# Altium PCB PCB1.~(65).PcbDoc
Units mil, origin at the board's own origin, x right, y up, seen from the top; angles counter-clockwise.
Board outline 6000 x 4000 mil, 2 copper layers (Top Layer, Bottom Layer); 40 components, 29 nets, 164 pads, 123 vias.
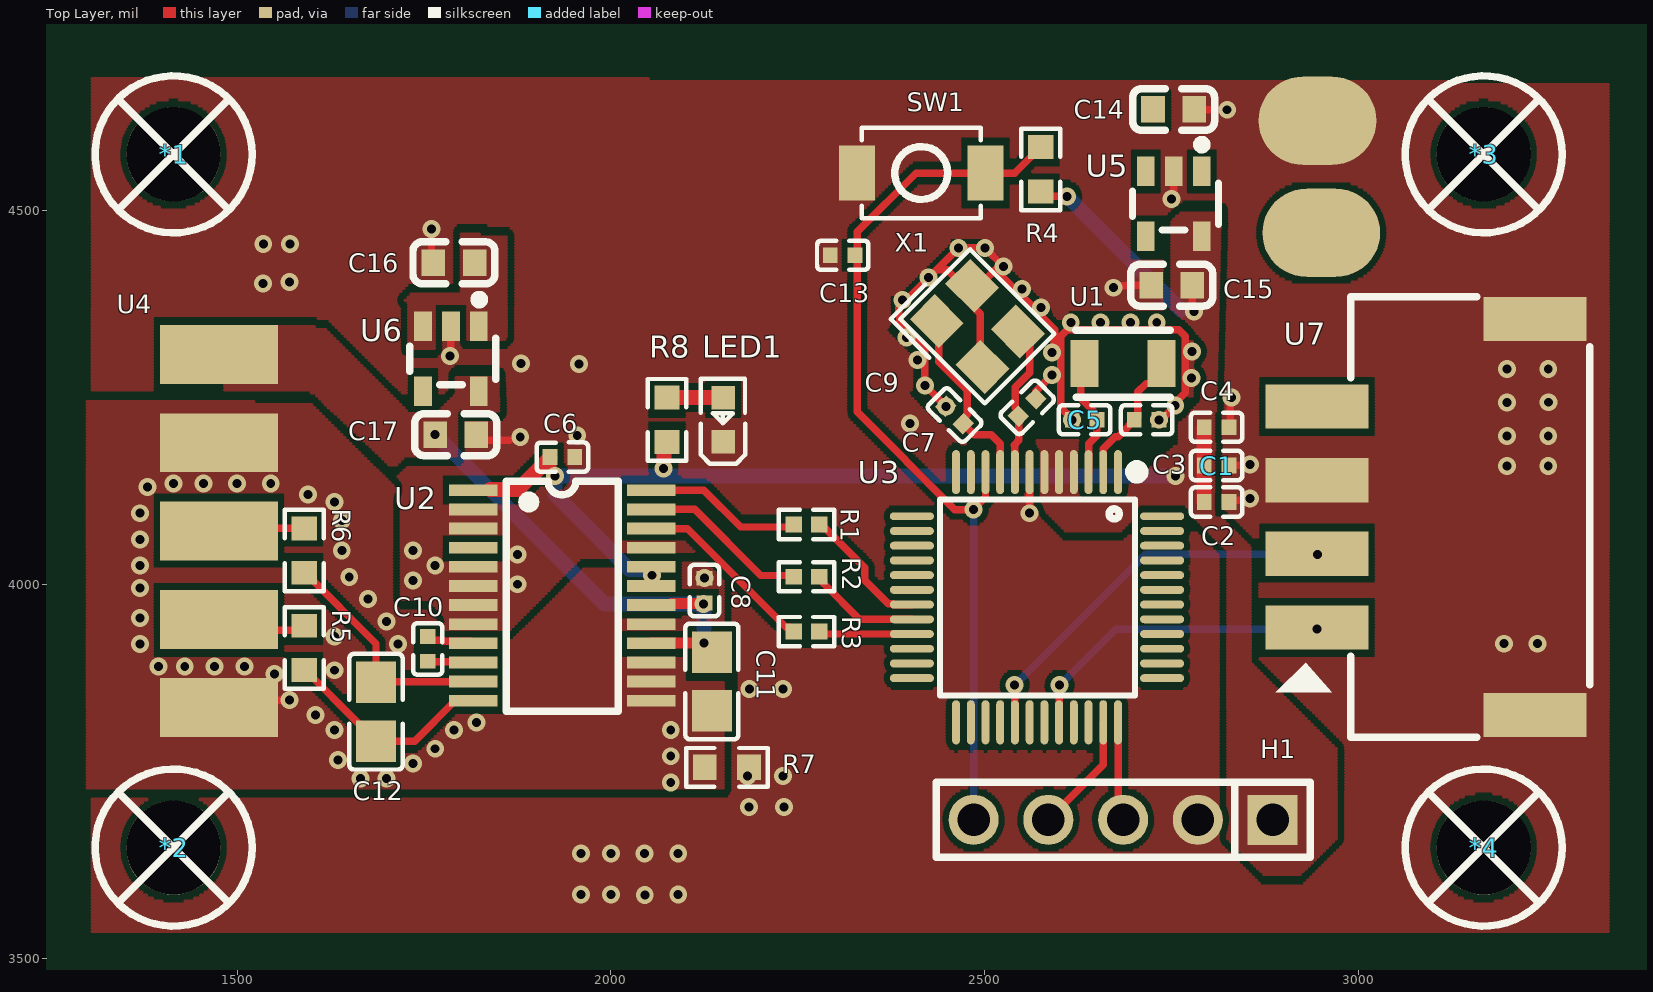
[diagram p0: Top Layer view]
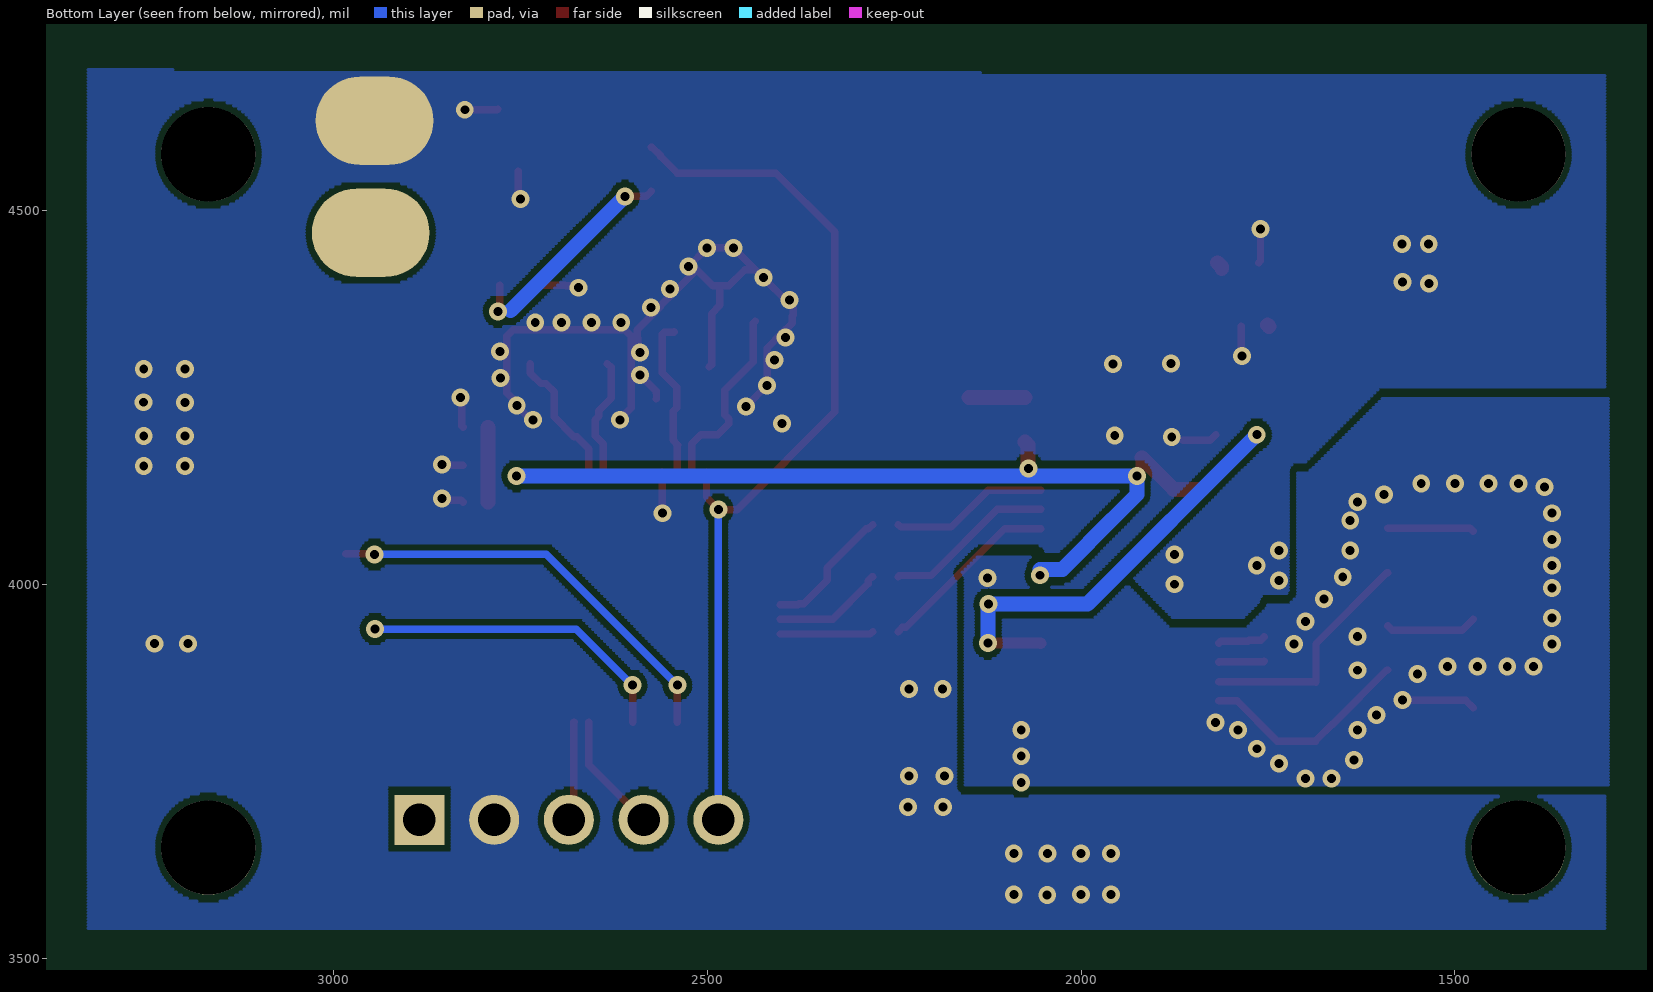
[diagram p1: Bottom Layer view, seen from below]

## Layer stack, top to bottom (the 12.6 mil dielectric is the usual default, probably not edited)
Top Solder: solder mask 0.4, Solder Resist, Dk 3.5
Top Layer: signal copper 1.4
Dielectric 1: dielectric 12.6, FR-4, Dk 4.8
Bottom Layer: signal copper 1.4
Bottom Solder: solder mask 0.4, Solder Resist, Dk 3.5

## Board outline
1000,1000 7000,1000 7000,5000 1000,5000

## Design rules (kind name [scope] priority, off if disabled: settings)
Clearance [All] p1: gap=8 ignorepadtopadclearanceinfootprint=FALSE
ComponentClearance [All] p1: gap=0 collisioncheckmode=3 verticalgap=0 showdistances=FALSE
HoleSize [All] p1: absolutevalues=TRUE maxlimit=130 minlimit=1 maxpercent=80.000 minpercent=20.000
MinimumSolderMaskSliver [All] p1: minsoldermaskwidth=4
PlaneConnect [All] p1: planeconnectstyle=Direct reliefexpansion=20 reliefentries=4 reliefconductorwidth=10 reliefairgap=10
PolygonConnect [All] p1: connectstyle=Direct reliefconductorwidth=10 reliefentries=4 polygonreliefangle="90 Angle" airgapwidth=10
RoutingVias [All] p1: holewidth=28 width=50 viastyle="Through Hole" minholewidth=28 minwidth=50 maxholewidth=28 maxwidth=50
SilkToSilkClearance [All] p1: silktosilkclearance=2
SilkToSolderMaskClearance [IsPad] p1: minsilkscreentomaskgap=2 clearancetoexposedcopper=TRUE
SolderMaskExpansion [All] p1: expansion=0 istentingtop=FALSE
SupplyNets "Schematic Supply Nets_2" [InNet('6V')] p1: voltage=0.000
SupplyNets "Schematic Supply Nets" [InNet('3V3')] p2: voltage=0.000
SupplyNets "Schematic Supply Nets_4" [InNet('5V')] p3: voltage=0.000
SupplyNets "Schematic Supply Nets_3" [InNet('DGND')] p4: voltage=0.000
SupplyNets "Schematic Supply Nets_1" [InNet('AGND')] p5: voltage=0.000
Width [All] p1: maxlimit=50 minlimit=10 preferedwidth=10
24 further rules are at their usual default settings.

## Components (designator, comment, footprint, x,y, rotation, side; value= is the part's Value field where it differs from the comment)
*1 "螺丝孔_1" M3螺丝 1415,4575 r0 top
*2 "螺丝孔_1" M3螺丝 1415,3647.74 r0 top
*3 "螺丝孔_1" M3螺丝 3167.2,4575 r0 top
*4 "螺丝孔_1" M3螺丝 3167.2,3647.74 r0 top
C1 "cc0402krx7r7bb104" C0402 2810,4158.83 r0 top value=100nF
C2 "cc0402jrnpo9bn220" C0402 2716.54,4220 r180 top value=22pF
C3 "cc0402krx7r7bb104" C0402 2810,4110 r0 top value=100nF
C4 "cc0402krx7r7bb104" C0402 2810,4210 r180 top value=100nF
C5 "cc0402jrnpo9bn220" C0402 2633.46,4220 r0 top value=22pF
C6 "cc0402krx7r7bb104" C0402 1935,4170 r0 top value=100nF
C7 "cc0402jrnpo9bn180" C0402 2556.7,4236.7 r45 top value=18pF
C8 "cc0402krx7r7bb104" C0402 2125,3991.54 r90 top value=100nF
C9 "cc0402jrnpo9bn180" C0402 2459.68,4226.29 r315 top value=18pF
C10 "cc0402krx7r7bb104" C0402 1755,3913.46 r90 top value=100nF
C11 "cl21b103kbannnc" C0805 2135,3870 r270 top value=10nF
C12 "cl21b103kbannnc" C0805 1685.78,3829.55 r270 top value=10nF
C13 "cc0402krx7r7bb104" C0402 2310,4440 r0 top value=100nF
C14 "cga0603x5r105k500jt" C0603 2752.56,4635 r0 top value=1uF
C15 "cga0603x5r105k500jt" C0603 2750,4400 r180 top value=1uF
C16 "cga0603x5r105k500jt" C0603 1790,4430 r180 top value=1uF
C17 "cga0603x5r105k500jt" C0603 1792.44,4200 r0 top value=1uF
H1 "pz254v-11-05p" HDR-TH_5P-P2.54-V-M 2685,3685 r180 top
LED1 "ltst-c190kskt" LED0603-RD 2150,4220 r90 top
R1 "frc0402f47r0ts" R0402 2261.76,4079.9 r0 top value=47Ω
R2 "frc0402f47r0ts" R0402 2261.76,4010.1 r0 top value=47Ω
R3 "frc0402f47r0ts" R0402 2261.76,3936.58 r0 top value=47Ω
R4 "frc0603f1002ts" R0603 2575,4555 r270 top value=10kΩ
R5 "frc0603f1000ts" R0603 1590,3915 r270 top value=100Ω
R6 "frc0603f1000ts" R0603 1590,4045 r270 top value=100Ω
R7 "0603waf0000t5e" R0603 2155,3755 r0 top value=0Ω
R8 "0603waf1001t5e" R0603 2075,4220 r270 top value=1kΩ
SW1 "ts-1088-ar02016" SW-SMD_L3.9-W3.0-P4.45 2415,4550 r0 top
U1 "fc31m2-32.768-ntlnndtl" CRYSTAL-SMD_L3.2-W1.5 2685,4295 r0 top value=32.768kHz
U2 "ads1232ipwr" TSSOP-24_L7.8-W4.4-P0.65-LS6.4-BL 1935,3985 r270 top
U3 "stm32g031c8t6" LQFP-48_L7.0-W7.0-P0.50-LS9.0-BL 2569.84,3982.68 r180 top
U4 "5个焊盘" "5个焊盘 - duplicate" 1475.75,4307.38 r270 top
U5 "tps7a2033pdbvr" SOT-23-5_L2.9-W1.6-P0.95-LS2.8-BR 2752.56,4508.8 r90 top
U6 "tps7a2050pdbvr" SOT-23-5_L2.9-W1.6-P0.95-LS2.8-BR 1786.01,4301.56 r90 top
U7 "bx-xh2.54-4pwt" CONN-SMD_4P-P2.50_BX-XH2.54-4PWT 3090,4090 r90 top
X1 "x32258mob4si" CRYSTAL-SMD_4P-L3.2-W2.5-BL 2490,4345 r315 top value=8MHz

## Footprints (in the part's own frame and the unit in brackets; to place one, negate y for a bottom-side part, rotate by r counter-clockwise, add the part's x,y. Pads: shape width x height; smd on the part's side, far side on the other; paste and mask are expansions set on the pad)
"5个焊盘 - duplicate" [mm]
  rect 2x4 smd: 1(0,0) 2(3,0) 3(6.001,0) 4(9,0) 5(12,0)
C0402 [mm]
  rect 0.5x0.54 smd: 1(-0.42,0) 2(0.42,0)
  silkscreen extent -0.87,-0.5 0.87,0.5
C0603 [mm]
  rect 0.8x0.9 smd: 1(-0.7,0) 2(0.7,0)
  silkscreen extent -1.39,-0.71 1.39,0.71
C0805 [mm]
  rect 1.41x1.35 smd paste-100 mask+0.051: 1(-1,0) 2(1,0)
  silkscreen extent -1.96,-0.9 1.96,0.9
CONN-SMD_4P-P2.50_BX-XH2.54-4PWT [mm]
  rect 1.5x3.5 smd paste+0 mask+0.05: 1(-3.75,3.7) 2(-1.25,3.7) 3(1.25,3.7) 4(3.75,3.7) 5(6.73,-3.7) 6(-6.73,-3.7)
  silkscreen extent -7.49,-5.57 7.49,5.1
CRYSTAL-SMD_4P-L3.2-W2.5-BL [mm]
  rect 1.4x1.2 smd: 1(-1.1,-0.85) 2(1.1,-0.85) 3(1.1,0.85) 4(-1.1,0.85)
  silkscreen extent -2.26,-1.91 2.03,1.68
CRYSTAL-SMD_L3.2-W1.5 [mm]
  rect 0.95x1.6 smd: 1(-1.308,0) 2(1.308,0)
  silkscreen extent -1.6,-1.14 1.6,1.14
HDR-TH_5P-P2.54-V-M [mm]
  rect 1.7x1.7 hole 1.1: 1(-5.08,0)
  round 1.7 hole 1.1: 2(-2.54,0) 3(0,0) 4(2.54,0) 5(5.08,0)
  silkscreen extent -6.35,-1.27 6.35,1.27
LED0603-RD [mm]
  rect 0.8x0.8 smd: 1(-0.749,0) 2(0.749,0)
  silkscreen extent -1.49,-0.75 1.39,0.76
LQFP-48_L7.0-W7.0-P0.50-LS9.0-BL [mm]
  oval 0.27x1.5 smd paste+0 mask+0.05: 1(-2.75,-4.25) 2(-2.25,-4.25) 3(-1.75,-4.25) 4(-1.25,-4.25) 5(-0.75,-4.25) 6(-0.25,-4.25) 7(0.25,-4.25) 8(0.75,-4.25) 9(1.25,-4.25) 10(1.75,-4.25) 11(2.25,-4.25) 12(2.75,-4.25) 25(2.75,4.25) 26(2.25,4.25) 27(1.75,4.25) 28(1.25,4.25) 29(0.75,4.25) 30(0.25,4.25) 31(-0.25,4.25) 32(-0.75,4.25) 33(-1.25,4.25) 34(-1.75,4.25) 35(-2.25,4.25) 36(-2.75,4.25)
  oval 1.5x0.27 smd paste+0 mask+0.05: 13(4.25,-2.75) 14(4.25,-2.25) 15(4.25,-1.75) 16(4.25,-1.25) 17(4.25,-0.75) 18(4.25,-0.25) 19(4.25,0.25) 20(4.25,0.75) 21(4.25,1.25) 22(4.25,1.75) 23(4.25,2.25) 24(4.25,2.75) 37(-4.25,2.75) 38(-4.25,2.25) 39(-4.25,1.75) 40(-4.25,1.25) 41(-4.25,0.75) 42(-4.25,0.25) 43(-4.25,-0.25) 44(-4.25,-0.75) 45(-4.25,-1.25) 46(-4.25,-1.75) 47(-4.25,-2.25) 48(-4.25,-2.75)
  silkscreen extent -3.59,-4.46 3.3,3.34
M3螺丝 [mil]
  round 126 hole 126 paste-99999 mask+4: 1(0,0)
  silkscreen extent -105,-105 105,105
R0402 [mm]
  rect 0.566x0.54 smd paste-100 mask+0.051: 1(-0.433,0) 2(0.433,0)
  silkscreen extent -0.94,-0.5 0.94,0.5
R0603 [mil]
  rect 31.75x34.02 smd paste-3937.01 mask+2: 1(-29.66,0) 2(29.66,0)
  silkscreen extent -55,-26 55,26
SOT-23-5_L2.9-W1.6-P0.95-LS2.8-BR [mm]
  rect 1x0.6 smd paste+0 mask+0.05: 1(1.1,-0.95) 2(1.1,0) 3(1.1,0.95) 4(-1.1,0.95) 5(-1.1,-0.95)
  silkscreen extent -0.89,-1.52 2.16,1.4
SW-SMD_L3.9-W3.0-P4.45 [mm]
  rect 1.23x1.86 smd: 1(-2.185,0) 2(2.185,0)
  silkscreen extent -2.03,-1.54 2.03,1.54
TSSOP-24_L7.8-W4.4-P0.65-LS6.4-BL [mm]
  rect 0.4x1.65 smd: 1(-3.575,-3.023) 2(-2.925,-3.023) 3(-2.275,-3.023) 4(-1.625,-3.023) 5(-0.975,-3.023) 6(-0.325,-3.023) 7(0.325,-3.023) 8(0.975,-3.023) 9(1.625,-3.023) 10(2.275,-3.023) 11(2.925,-3.023) 12(3.575,-3.023) 13(3.575,3.023) 14(2.925,3.023) 15(2.275,3.023) 16(1.625,3.023) 17(0.975,3.023) 18(0.325,3.023) 19(-0.325,3.023) 20(-0.975,3.023) 21(-1.625,3.023) 22(-2.275,3.023) 23(-2.925,3.023) 24(-3.575,3.023)
  silkscreen extent -3.89,-1.91 3.94,1.9

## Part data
C1 C3 C4 C6 C8 C10 C13: "容值:100nF;精度:±10%;额定电压:16V;温度系数:X7R;", JLCPCB Part Class="Extended Part", LCSC Part Name="100nF ±10% 16V", Manufacturer=YAGEO(国巨), ManufacturerPart=CC0402KRX7R7BB104, Temperature Coefficient=X7R, Tolerance=±10%, Voltage Rating=16V
C2 C5: "容值:22pF;精度:±5%;额定电压:50V;温度系数:NP0;", JLCPCB Part Class="Extended Part", LCSC Part Name="22pF ±5% 50V", Manufacturer=YAGEO(国巨), ManufacturerPart=CC0402JRNPO9BN220, Temperature Coefficient=NP0, Tolerance=±5%, Voltage Rating=50V
C7 C9: "容值:18pF;精度:±5%;额定电压:50V;温度系数:NP0;", JLCPCB Part Class="Extended Part", LCSC Part Name="18pF ±5% 50V", Manufacturer=YAGEO(国巨), ManufacturerPart=CC0402JRNPO9BN180, Temperature Coefficient=NP0, Tolerance=±5%, Voltage Rating=50V
C11 C12: "容值:10nF;精度:±10%;额定电压:50V;温度系数:X7R;", JLCPCB Part Class="Basic Part", LCSC Part Name="10nF ±10% 50V", Manufacturer=SAMSUNG(三星), ManufacturerPart=CL21B103KBANNNC, Temperature Coefficient=X7R, Tolerance=±10%, Voltage Rating=50V
C14 C15 C16 C17: "容值:1uF;精度:±10%;额定电压:50V;温度系数:X5R;", JLCPCB Part Class="Extended Part", LCSC Part Name="1uF ±10% 50V 停产", Manufacturer=HRE(芯声), ManufacturerPart=CGA0603X5R105K500JT, Temperature Coefficient=X5R, Tolerance=±10%, Voltage Rating=50V
H1: "插针结构:1x5P;间距:2.54mm;行距:-;圆针/方针:方针;安装方式:直插;排数:单排;总PIN位数:5P;额定电流:3A;额定电压:250V;配合针长度:6mm;塑高:2.5mm;端接针长度:3mm;触头材质:黄铜;触头镀层:-;工作温度:-40℃~+105℃;颜色:黑色;", Color=黑色, Current Rating=3A, JLCPCB Part Class="Extended Part", LCSC Part Name="1x5P 间距:2.54mm 方针 直插", Manufacturer=XFCN(兴飞), ManufacturerPart=PZ254V-11-05P, Operating Temperature=-40℃~+105℃, Voltage Rating (Max)=250V
LED1: "灯头类型:-;发光颜色:黄色;正向压降(Vf):2.1V;功率:75mW;正向电流:20mA;波长:584.5nm~597nm;二极管配置:独立二极管;透镜颜色:无色透明透镜;色温:-;发光强度:104mcd;发光角度:130°;载带方式:-;工作温度:-30℃~+85℃;", Color Temperature=-, Forward Current=20mA, Illumination Color=黄色, JLCPCB Part Class="Extended Part", LCSC Part Name=黄灯, Lens Color=无色透明透镜, Manufacturer=LITEON(光宝), ManufacturerPart=LTST-C190KSKT, Operating Temperature=-30℃~+85℃, Power(Watts)=75mW, Voltage - Forward(Vf)=2.1V
R1 R2 R3: "电阻类型:厚膜电阻;阻值:47Ω;精度:±1%;功率:62.5mW;工作电压:50V;温度系数:±100ppm/℃;", JLCPCB Part Class="Extended Part", LCSC Part Name="47Ω ±1% 62.5mW 厚膜电阻", Manufacturer=FOJAN(富捷), ManufacturerPart=FRC0402F47R0TS, Operating Temperature=-55℃~+155℃, Power(Watts)=62.5mW, Temperature Coefficient=±100ppm/℃, Tolerance=±1%, Voltage-Supply(Max)=50V
R4: "电阻类型:厚膜电阻;阻值:10kΩ;精度:±1%;功率:100mW;工作电压:75V;温度系数:±100ppm/℃;", JLCPCB Part Class="Extended Part", LCSC Part Name="10kΩ ±1% 100mW 厚膜电阻", Manufacturer=FOJAN(富捷), ManufacturerPart=FRC0603F1002TS, Operating Temperature=-55℃~+155℃, Power(Watts)=100mW, Temperature Coefficient=±100ppm/℃, Tolerance=±1%, Voltage-Supply(Max)=75V
R5 R6: "电阻类型:厚膜电阻;阻值:100Ω;精度:±1%;功率:100mW;工作电压:75V;温度系数:±100ppm/℃;", JLCPCB Part Class="Extended Part", LCSC Part Name="100Ω ±1% 100mW 厚膜电阻", Manufacturer=FOJAN(富捷), ManufacturerPart=FRC0603F1000TS, Operating Temperature=-55℃~+155℃, Power(Watts)=100mW, Temperature Coefficient=±100ppm/℃, Tolerance=±1%, Voltage-Supply(Max)=75V
R7: "电阻类型:厚膜电阻;阻值:0Ω;精度:±1%;功率:100mW;工作电压:75V;温度系数:-;", JLCPCB Part Class="Basic Part", LCSC Part Name="0Ω ±1% 100mW 厚膜电阻", Manufacturer=UNI-ROYAL(厚声), ManufacturerPart=0603WAF0000T5E, Operating Temperature=-55℃~+155℃, Power(Watts)=100mW, Temperature Coefficient=-, Tolerance=±1%, Voltage-Supply(Max)=75V
R8: "电阻类型:厚膜电阻;阻值:1kΩ;精度:±1%;功率:100mW;工作电压:75V;温度系数:±100ppm/℃;", JLCPCB Part Class="Basic Part", LCSC Part Name="1kΩ ±1% 100mW 厚膜电阻", Manufacturer=UNI-ROYAL(厚声), ManufacturerPart=0603WAF1001T5E, Operating Temperature=-55℃~+155℃, Power(Watts)=100mW, Temperature Coefficient=±100ppm/℃, Tolerance=±1%, Voltage-Supply(Max)=75V
SW1: "电路结构:单刀单掷;按钮形状:圆形按钮;作用力:1.6N;安装方式:立贴;开关长度:3.9mm;开关宽度:3mm;开关高度:2mm;带支架:不带支架;触点电流:50mA;额定电压:12V;带灯:-;工作寿命:10万次;", Actuator/Cap Color=黑色, Contact Current=50mA, IP Rating=-, JLCPCB Part Class="Basic Part", LCSC Part Name="3.9*3*2mm 立贴 轻触开关", Manufacturer=XUNPU(讯普), ManufacturerPart=TS-1088-AR02016, Operating Force=1.6N, Operating Temperature=-30℃~+80℃, Voltage Rating=12V
U1: "晶振类型:贴片晶振;频率:32.768kHz;常温频差:±10ppm;负载电容:12.5pF;频率稳定度:±10ppm;", Equivalent Series Resistance(ESR)=70kΩ, Frequency Stability=±10ppm, JLCPCB Part Class="Extended Part", LCSC Part Name="3215 2P 32.768kHz 12.5pF ±10ppm -40~+85℃(±10ppm)", Load Capacitance=12.5pF, Manufacturer=HCI(杭晶), ManufacturerPart=FC31M2-32.768-NTLNNDTL, Operating Temperature=-40℃~+85℃
U2: "分辨率(位):24;采样率:10Hz;工作电压:2.7V~5.3V;接口类型:SPI;", Clock Frequency=4.9152MHz；200kHz~8MHz, JLCPCB Part Class="Extended Part", LCSC Part Name="用于桥式传感器的24bit 模数转换器", Manufacturer=TI(德州仪器), ManufacturerPart=ADS1232IPWR, Operating Temperature=-40℃~+105℃, Quiescent Current (Iq)=1.3uA, Temperature Sensors=内置, Voltage - Supply=2.7V~5.3V, Voltage Reference=外置, Voltage Reference Drift=-
U3: "CPU内核:ARM Cortex-M0+;CPU最大主频:64MHz;CPU位数:32 Bit;", JLCPCB Part Class="Extended Part", LCSC Part Name="主流Arm Cortex-M0+ MCU，具有64 KB Flash存储器、8 KB RAM、64 MHz CPU、2x USART、定时器、ADC和通信接口，1.7-3.6V", Manufacturer=ST(意法半导体), ManufacturerPart=STM32G031C8T6, Operating Temperature=-40℃~+85℃, Voltage - Supply=1.7V~3.6V
U5: "输出类型:固定;最大输入电压:6V;输出电压:3.3V;输出电流:300mA;输出极性:正极;", Dropout Voltage=140mV@(300mA), JLCPCB Part Class="Extended Part", LCSC Part Name="具有高 PSRR 的 300mA、超低噪声、低 IQ、低压降 (LDO) 线性稳压器", Manufacturer=TI(德州仪器), ManufacturerPart=TPS7A2033PDBVR, Maximum Input Voltage=6V, Operating Temperature=-40℃~+125℃@(Tj), Output Current=300mA, Output Voltage=3.3V, standby current=15uA
U6: "输出极性:正极;工作电压:6V;输出电压:5V;输出电流:300mA;电源纹波抑制比(PSRR):65dB@(100Hz);输出类型:固定;", JLCPCB Part Class="Extended Part", LCSC Part Name="800mV~5.5V 300mA 6V", Manufacturer=TI(德州仪器), ManufacturerPart=TPS7A2050PDBVR, Operating Temperature=-40℃~+125℃@(Tj), Output Current=300mA, Output Voltage=5V, Power Supply Rejection Ratio (PSRR)=65dB@(100Hz), standby current=6.5uA, Voltage - Supply=6V, Voltage Dropout=140mV@(300mA)
U7: "插针结构:1x4P;间距:2.5mm;安装方式:卧贴;参考系列:XH;总PIN数:4P;排数:1;每排PIN数:4;行距:-;额定电流:3A;触头材质:黄铜;触头镀层:锡;工作温度:-25℃~+85℃;", Color=米色, Current Rating=3A, Flame Retardant Rating=-, JLCPCB Part Class="Extended Part", LCSC Part Name="1x4P 间距:2.5mm 卧贴 系列:XH", Manufacturer=Bossie(博锡), ManufacturerPart=BX-XH2.54-4PWT, Operating Temperature=-25℃~+85℃, Voltage Rating=250V
X1: "晶振类型:贴片晶振;频率:8MHz;常温频差:±10ppm;负载电容:12pF;频率稳定度:±20ppm;", Equivalent Series Resistance(ESR)=180Ω, Frequency Stability=±20ppm, JLCPCB Part Class="Extended Part", LCSC Part Name="YSX321SL 8MHZ 4P 3225 12PF ±10PPM -40~85℃ (±20PPM)", Load Capacitance=12pF, Manufacturer=YXC(扬兴晶振), ManufacturerPart=X32258MOB4SI, Normal temperature Frequency Tolerance=±10ppm, Operating Temperature=-40℃~+85℃

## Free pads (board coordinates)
  oval 157.48x118.11 all layers, no hole: 7(2945,4620) 7(2950,4470)

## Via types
v1: diameter 24, hole 12, Top Layer to Bottom Layer, tented both sides, 123 vias

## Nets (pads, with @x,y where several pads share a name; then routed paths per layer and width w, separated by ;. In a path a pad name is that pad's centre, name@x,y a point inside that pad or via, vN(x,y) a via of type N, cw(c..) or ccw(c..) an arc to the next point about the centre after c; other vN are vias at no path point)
3V3: C1.1 C3.1 C4.2 C6.1 C15.1 H1.1 R4.2 R8.2 U2.1 U2.19 U2.20 U3.4 U3.5 U3.6 U5.5 | length 1596.3
  Top Layer w10: C6.1@1918.46,4169.21 1922.32,4165.35 1922.32,4147.68 v1(1925,4145) ; R4.2 2581.6,4518.74 v1(2610.11,4518.74) ; C15.1 2777.56,4367.44 v1(2780,4365)
  Top Layer w20: U2.1@1838.48,4126.91 1876.16,4126.91 C6.1@1918.46,4169.21 ; v1(2070,4155) 2070.77,4155.77 2070.77,4186.11 R8.2 ; C3.1 C4.2 C4.2@2793.46,4209.53
  Bottom Layer w10: 1990,4054.75 1990,4055.36 ; 2762.83,4366.01 2778.99,4366.01 v1(2780,4365)
  Bottom Layer w20: 1990,4054.75 2024.75,4020 v1@2055,4020 ; 1990,4055.36 1925,4120.36 v1(1925,4145) v1(2755,4145) ; v1(2610.11,4518.74) 2762.83,4366.01
  other v1: 2055.03,4012.07
5V: C8.1 C11.1 C17.1 U2.16 U2.18 U4.1 U6.5 | length 648.9
  Top Layer w10: v1(2123.61,3973.61) C8.1
  Top Layer w15: U2.16 2054.26,3921.28 v1(2124.74,3921.28) ; U2.18 2078.61,3972.21 2080.81,3974.42 2122.79,3974.42 v1(2123.61,3973.61)
  Bottom Layer w10: v1(2123.61,3973.61) v1@2124.17,3973.04 ; v1@2124.17,3921.85 v1(2124.74,3921.28)
  Bottom Layer w20: v1(1765,4200) 1991.39,3973.61 v1(2123.61,3973.61) ; v1@2124.17,3921.85 v1@2124.17,3973.04
6V: C14.1 C16.1 pad.7@2950,4470 U5.1 U5.3 U6.1 U6.3 U7.4 | length 12.7
  Top Layer w20: U6.3 U6.3@1750.43,4346.68 ; C16.1@1811.81,4422.28 1811.81,4424.25 C16.1
AGND: C8.2 C11.2 R7.1 U2.13 U2.14 U2.15 U2.17 U4.2 U4.5 | length 98.4
  Top Layer w10: U4.5 1485.81,3845 v1(1570,3845)
  other v1: 2080,3735 1665,3740 1700,3740 1735,3760 1635,3765 2080,3770 1765,3780 1630,3805 1790,3805 2080,3805 1820,3815 1605,3825 1550,3880 1630,3885 1395,3890 1430,3890 1470,3890 1510,3890 1370,3920 1715,3920 1630,3930 1700,3950 1370,3955 1675,3980 1370,3995 2125,4008.08 1650,4010 1370,4025 1640,4045 1370,4060 1640,4085 1370,4095 1630,4110 1595,4120 1380,4130 1415,4135 1455,4135 1500,4135 1545,4135
AINN1: R5.1 U4.4 | length 140.4
  Top Layer w10: U4.4 1490.33,3938.46 R5.1@1583.8,3938.46 ; R5.1@1583.8,3938.46 R5.1 ; R5.1@1583.8,3938.46 R5.1 ; R5.1@1583.8,3938.46 R5.1
AINP1: R6.1 U4.3 | length 115.7
  Top Layer w10: U4.3 1479.27,4074.66 R6.1
DGND: C1.2 C2.1 C3.2 C4.1 C5.1 C6.2 C7.2 C9.1 C13.1 C14.2 C15.2 C16.2 C17.2 H1.2 LED1.1 pad.7@2945,4620 R7.2 SW1.1 U2.2 U2.3 U2.5 U2.6 U2.7 U2.8 U2.21 U3.7 U5.2 U6.2 U7.3 U7.5 U7.6 X1.2 X1.4 | length 1632.1
  Top Layer w10: v1(1760,4475) 1760,4432.44 C16.2 ; v1(1785,4305) 1786.02,4306.02 U6.2 ; C17.2 1827.34,4192.66 1864.15,4192.66 ; v1(2390,4380) v1@2392.5,4377.5 ; v1(2395,4330) v1@2400.44,4335.44 ; v1@2419.14,4415.86 v1(2425,4410) ; v1(2447.98,4237.98) v1(2420,4265.96) 2420,4315.88 v1@2400.44,4335.44 ; X1.2 2494.18,4293.5 2494.18,4361.81 2483.04,4372.95 X1.4 ; v1(2525,4425) v1(2500,4450) v1(2465,4450) 2435.86,4420.86 ; v1(2550,4395) v1@2545,4390 ; v1(2560,4095) U3.7 ; C7.2 2567.83,4248.95 2567.83,4255.8 2568.39,4256.35 2568.39,4258.39 v1(2590,4280) ; v1(2590,4310) 2592.68,4312.68 2592.68,4329.07 2593.48,4329.87 2593.48,4340.64 2562.06,4372.06 2562.06,4372.94 v1@2545,4390 ; v1(2616.92,4220) 2616.92,4220.79 2601.8,4235.91 2601.8,4331.88 2610.36,4340.44 2759.64,4340.44 2768.2,4331.88 v1@2768.2,4311.26 ; v1(2672.21,4396.6) 2674.88,4399.28 2689.28,4399.28 2690,4400 C15.2 ; v1(2733.08,4220) 2737.92,4224.84 C2.1@2737.92,4225.63 ; C2.1@2733.08,4220.79 C2.1@2737.92,4225.63 ; v1(2750,4515) 2752.57,4517.56 U5.2 ; v1(2776.38,4275.61) v1@2768.2,4275.61 ; v1(2776.94,4311.26) v1@2768.2,4311.26 ; C14.2 2780.48,4634.64 v1(2824.25,4634.64) ; C3.2 2829.04,4112.5 2852.5,4112.5 v1(2855,4115) ; C1.2 2827.13,4159.41 2854.41,4159.41 v1(2855,4160) ; C4.1 2828.27,4211.73 2828.27,4248.27 v1(2830,4250) ; v1@2392.5,4377.5 v1(2425,4410) ; v1@2392.5,4377.5 2385,4370 2385,4360 2386.52,4358.48 2386.52,4349.36 v1@2400.44,4335.44 ; v1(2425,4410) 2435.86,4420.86 ; 2435.86,4420.86 2449.5,4420.86 2471.07,4399.29 X1.4 ; X1.4 2492.57,4399.29 2514.14,4420.86 v1@2545,4390 ; C2.1@2737.92,4225.63 2741.22,4225.63 v1(2754.71,4239.12) 2754.71,4242.91 2768.2,4256.4 v1@2768.2,4275.61 ; v1@2768.2,4275.61 v1@2768.2,4311.26
  other v1: 1960,3585 2000,3585 2045.24,3584.54 2090,3585 1960,3640 2000,3640 2045,3640 2090,3640 2184.44,3702.22 2231.16,3701.9 2182.87,3743.61 2229.91,3743.61 2185,3860 2230,3860 3194.27,3920.47 3239.27,3920.47 1875,4000 1735,4005 1765,4025 1875,4040 1735,4045 3198.6,4158.19 3253.6,4158.19 1878.69,4196.86 3198.6,4198.19 3253.6,4198.19 1954.92,4199.01 2400,4215 3198.6,4243.19 3254.06,4243.44 3198.6,4288.19 3253.6,4288.19 1880,4295 1957.05,4294.87 2410,4300 2615,4350 2655,4350 2695,4350 2730,4350 2575,4370 1534.72,4402.35 1570.25,4404.08 1535,4455 1570.83,4454.92
DOUT: R1.2 U3.19 | length 177.7
  Top Layer w10: R1.2 2284.43,4074.27 2287.1,4074.27 2339.33,4022.05 2339.33,4005.6 2370.72,3974.2 2376.77,3974.2 2378.14,3972.84 U3.19
NetC2_2: C2.2 U1.2 U3.2 | length 183.5
  Top Layer w10: U3.2 2658.54,4150.12 2658.54,4181.49 2674.61,4197.56 2678.35,4197.56 2704.84,4224.06 2704.84,4257.3 2716.05,4268.5 2722.8,4268.5 2736.5,4282.21 U1.2
NetC5_2: C5.2 U1.1 U3.3 | length 160.6
  Top Layer w10: U1.1 2628.5,4290 2628.5,4248.5 2645.16,4231.85 2645.16,4224.84 C5.2 2650,4198.85 2638.86,4187.71 2638.86,4150.12 U3.3
NetC7_1: C7.1 U3.8 X1.3 | length 214.9
  Top Layer w10: U3.8 U3.8 2540.35,4157.44 2540.35,4184.95 2539.11,4186.19 2545.56,4192.63 2545.56,4231.29 2540.91,4235.93 2540.91,4263.56 2560.11,4282.75 2560.11,4334.54 2557.33,4337.33 2545,4337.33 X1.3
NetC9_2: C9.2 U3.9 X1.1 | length 254.5
  Top Layer w10: X1.1 2438.5,4349.18 2438.5,4297.39 2476.34,4259.54 2476.34,4226.41 2471.37,4221.44 C9.2 2486.12,4199.85 2508.69,4199.85 2520.67,4187.86 2520.67,4157.44 2520.67,4150.04 U3.9
NetC10_1: C10.1 U2.10 | length 61.6
  Top Layer w10: C10.1 1755.74,3896.18 1815.25,3896.18 U2.10
NetC10_2: C10.2 U2.9 | length 64.7
  Top Layer w10: C10.2 1759.84,3925.16 1774.84,3925.16 1776.11,3923.89 1813.13,3923.89 U2.9
NetC12_1: C12.1 R6.2 U2.11 | length 317.4
  Top Layer w10: R6.2 1591.13,4015.34 1685.78,3920.69 C12.1 1686.7,3869.84 U2.11
NetC12_2: C12.2 R5.2 U2.12 | length 288.5
  Top Layer w10: R5.2 1591.13,3885.34 1663.53,3812.94 1664.21,3812.94 1685.78,3791.37 C12.2 1737.32,3790.18 1791.39,3844.26 U2.12
NetLED1_2: LED1.2 R8.1 | length 75.1
  Top Layer w20: R8.1 2075.09,4249.57 2149.91,4249.57 LED1.2
NetR1_1: R1.1 U2.24 | length 212.4
  Top Layer w10: U2.24 2124.37,4125.74 2173.51,4076.6 2241.41,4076.6 R1.1
NetR2_1: R2.1 U2.23 | length 228
  Top Layer w10: U2.23 2111.84,4100.15 2200.28,4011.71 2243.1,4011.71 R2.1
NetR3_1: R3.1 U2.22 | length 247.9
  Top Layer w10: U2.22 2102.21,4074.56 2234.55,3942.21 2239.09,3942.21 R3.1
NRST: C13.2 H1.5 R4.1 SW1.2 U3.10 | length 1214.7
  Top Layer w10: v1@2485,4099.91 2460.11,4099.91 2329.52,4230.5 2329.52,4471.33 2408.19,4550 SW1.2 2540.23,4550 2562.99,4572.76 2562.99,4573.78 2573.87,4584.66 R4.1 ; v1@2485,4100.37 2500.94,4116.31 U3.10
  Bottom Layer w10: H1.5 v1(2485,4100)
PDWN: R3.2 U3.21 | length 125
  Top Layer w10: R3.2 2281.91,3933.47 U3.21
SCLK: R2.2 U3.20 | length 149.6
  Top Layer w10: R2.2 2279.3,4010.1 2284.93,4004.47 2284.93,4000.51 2332.3,3953.15 U3.20
SWCLK: H1.3 U3.36 | length 133.2
  Top Layer w10: U3.36 2678.23,3815.24 2678.23,3691.77 H1.3
SWDIO: H1.4 U3.35 | length 160.8
  Top Layer w10: H1.4 2658.42,3758.42 U3.35
USART1_RX: U3.32 U7.1 | length 426.3
  Top Layer w10: U3.32 2599.37,3864.37 v1(2600,3865) ; U7.1@2943.55,3942.36 U7.1
  Bottom Layer w10: v1(2600,3865) 2675,3940 2944.44,3940 v1(2944.49,3940.05)
USART1_TX: U3.29 U7.2 | length 566.6
  Top Layer w10: v1(2540,3865) 2540.31,3864.69 U3.29 ; U7.2 U7.2@2983.7,4040.78
  Bottom Layer w10: v1(2540,3865) 2715,4040 v1(2945,4040)
USART2_RX: U3.14
USART2_TX: U3.13
pads on no net: *1.1 *2.1 *3.1 *4.1 U2.4 U3.1 U3.11 U3.12 U3.15 U3.16 U3.17 U3.18 U3.22 U3.23 U3.24 U3.25 U3.26 U3.27 U3.28 U3.30 U3.31 U3.33 U3.34 U3.37 U3.38 U3.39 U3.40 U3.41 U3.42 U3.43 U3.44 U3.45 U3.46 U3.47 U3.48 U5.4 U6.4

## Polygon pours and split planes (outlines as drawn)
6V on Top Layer "NONET_L-01_P-001" (hatched Horizontal grid 4 track 5, remove dead copper, pour order 23): 1800,4470 1800,4390 1735,4390 1725,4380 1730,4375 1730,4315 1770,4315 1775,4310 1775,4375 1785,4375 1805,4355 1805,4325 1855,4325 1860,4330 1860,4465
6V on Top Layer "NONET_L-01_P-001" (hatched Horizontal grid 4 track 5, remove dead copper, pour order 22): 3050,4530 3050,4415 3050,4380 3040,4355 3040,4190 2865,4190 2855,4200 2855,4540 2785,4540 2775,4530 2770,4535 2770,4580 2740,4580 2730,4570 2735,4565 2735,4525 2675,4525 2610,4590 2610,4615 2290,4615 2065,4390 1800,4390 1800,4525 1955,4680 2740,4680 2750,4670 2750,4600 2840,4600 2895,4545 3025,4545
3V3 on Top Layer "NONET_L-01_P-001" (hatched Horizontal grid 4 track 5, remove dead copper, pour order 21): 2765,4500 2750,4485 2750,4365 2755,4365 2795,4325 2790,4320 2790,4245 2760,4215 2760,4185 2755,4185 2670,4110 2660,4110 2630,4110 2630,4195 2570,4195 2570,4110 2610,4070 2680,4070 2715,4105 2765,4105 2825,4045 2825,3660 2875,3610 2920,3610 2970,3660 2970,3780 2855,3895 2855,4050 2805.18,4099.82 2815.06,4500
AGND on Top Layer "NONET_L-01_P-001" (hatched Horizontal grid 4 track 5, remove dead copper, pour order 7): 1520,4245 1595,4245 1710,4130 1710,3975 1750,3975 1782.5,3942.5 1862.5,3942.5 1870,3935 1965,4030 2135,4030 2140,4035 2150,4025 2150,3725 1300,3725 1300,4245
DGND on Top Layer "NONET_L-01_P-001" (hatched Horizontal grid 4 track 5, remove dead copper, pour order 15): 1306.25,4678.75 1306.25,3535.55 3333.75,3535.55 3333.75,4671.25
5V on Top Layer "NONET_L-01_P-001" (hatched Horizontal grid 4 track 5, remove dead copper, pour order 9): 1848.57,4280 1828.57,4280 1793.57,4280 1793.57,4255 1773.57,4235 1723.57,4235 1613.57,4345 1483.57,4345 1483.57,4255 1600,4255 1635,4225 1708.57,4155 1723.57,4170 1793.57,4170 1793.57,4230 1798.57,4235 1803.57,4230 1850,4230
DGND on Top Layer "NONET_L-01_P-001" (hatched Horizontal grid 4 track 5, remove dead copper, pour order 5): 1720,4115 1785,4115 1860,4115 1915,4060 2090,4060 2090,4040 2085,4035 1960,4035 1860,3935 1785,3935 1785,3950 1755,3980 1720,3980
DGND on Bottom Layer "NONET_L-01_P-001" (hatched Horizontal grid 4 track 5, remove dead copper, pour order 16): 3327.5,4688.42 3327.5,3539.09 1300,3539.09 1300,4680.91
AGND on Bottom Layer "NONET_L-01_P-001" (hatched Horizontal grid 4 track 5, remove dead copper, pour order 12): 1295,4250 1595,4250 1695,4150 1710,4150 1710,3985 1720,3975 1750,3975 1750,3970 1780,3940 1880,3940 1980,4040 2135,4040 2160,4015 2155,4010 2155,3730 1295,3730

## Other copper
Top Layer:
  pour cut-out: 2380,4380 2455,4455 2455,4460 2495,4460 2590,4365 2590,4360 2600,4350 2615,4365 2735.08,4365 2770,4330.08 2770,4235 2735,4200 2595,4200 2550,4245 2520,4215 2440,4215 2400,4255 2405,4260 2405,4305 2370,4340 2375,4345 2375,4385

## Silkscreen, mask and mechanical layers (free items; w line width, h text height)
Mechanical 1:
  lines w10: 1295,3530 3325,3530 3325,4685 1295,4685 1295,3530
